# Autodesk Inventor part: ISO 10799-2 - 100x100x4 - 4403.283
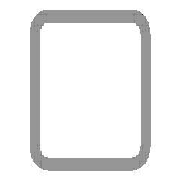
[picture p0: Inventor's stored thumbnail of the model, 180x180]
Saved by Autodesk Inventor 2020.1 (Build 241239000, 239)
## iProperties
Created: 2019-10
Part Number: ISO 10799-2 - 100x100x4 - 4403.283
Material: Stainless Steel
Description: Structural steels - Cold-formed, welded, structural hollow sections
Document SubType Name: Modeling
Standard: ISO
Designer: Synergysoft Dell02
Standard Revision: First edition 2011-09-15
Standards Organization: ISO
Language: en-US
Size Designation: 100x100x4
Categories: <MemberInstance><Categories><Category DisplayName="Structural Shapes" InternalName="089c4875-fa83-4c05-b084-43b9cc11f5ed" Mnemonic="GRDR"><CategoryParameter Dis
Stock Number: 100x100x4
Density: 8 g/cm^3
Appearance: Semi-Polished
_CCFamilyMember: 43
_CCFamilyDisplayName: ISO 10799-2 (Square) - Structural steels - Cold-formed, welded, structural hollow sections
_FrameMemberDoc: Frame Member File
_Version: 15.0.0
_GetPNFromCC: 1
G_L: 4403.283 mm
G_W: 100.000 mm
G_H: 100.000 mm
+F0EB09D6-E95E-4F0D-A0A9-255925CD8DEC+CUTDETAIL1: Miter 45.00 deg
+C07F1630-128D-4BA2-99A7-A66D939FA75D+CUTDETAIL2: Miter 22.50 deg
IsCustomPart: 1
Author: Synergysoft Dell02
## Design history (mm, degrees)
node "Start Plane"
node "End Plane"
sketch "Sketch"
  geometry: L1 (-50, -42)-(-50, 42); L2 (-42, 50)-(42, 50); L3 (50, 42)-(50, -42); L4 (42, -50)-(-42, -50); L5 (-42, 46)-(42, 46); L6 (46, 42)-(46, -42); L7 (42, -46)-(-42, -46); L8 (-46, -42)-(-46, 42); L9 (0, 72.32)-(0, -72.32) reference; L10 (-72.32, 0)-(72.32, 0) reference; A1 r 8 centre (-42, -42) between (-50, -42) and (-42, -50); A2 r 8 centre (42, 42) between (50, 42) and (42, 50); A3 r 8 centre (-42, 42) between (-42, 50) and (-50, 42); A4 r 8 centre (42, -42) between (42, -50) and (50, -42); A5 r 4 centre (-42, 42) between (-42, 46) and (-46, 42); A6 r 4 centre (42, 42) between (46, 42) and (42, 46); A7 r 4 centre (42, -42) between (42, -46) and (46, -42); A8 r 4 centre (-42, -42) between (-46, -42) and (-42, -46)
  constraints: 16 end point, 16 point on circle, 8 centre point, 8 tangent, 4 parallel, 3 equal radius, 2 perpendicular, 7 other
  dimensions: "d7" = 8 radius of A1 (= G_IR); "d9" = 100 distance between parallel lines of L1 L3 (= G_W); "d11" = 100 distance between parallel lines of L2 L4 (= G_H); "d12" = 4 distance between parallel lines of L3 L6 (= G_T); "d15" = 50 distance between parallel lines of L9 L3 (= 0.5 x d9); "d16" = 50 distance between parallel lines of L2 L10 (= 0.5 x d11)
extrude "Body" new body sketch "Sketch" stored distance "d3" = 4403.28302 (= G_L); taper "d4" = 0 deg
node "Driven Length"
  sketch "Sketch3"
    geometry: L1 (0, 0)-(10, 0) reference
    constraints: 2 end point, 1 horizontal
  workplane "Work Plane3"
  sketch "Sketch4"
    geometry: L1 (-2, -114.178)-(12, -114.178) reference; L2 (-2, 4289.105)-(12, 4289.105) reference
    dimensions: "d18" = 4403.28302 distance between parallel lines of L1 L2 (derived)
workplane "Work Plane4"
split "Split1"
workplane "Work Plane5"
split "Split2"
body "Solid1"
other parameters: "G_W" = 100 [user parameter; used in 1 equation term], "G_H" = 100 [user parameter; used in 1 equation term], "G_T" = 4 [user parameter; used in 1 equation term], "G_IR" = 8 [user parameter; used in 1 equation term], "G_L" = 4403.28302 (= d18) [user parameter; used in 1 equation term], "G_OFFSET_START" = 114.17786 [user parameter; used in 1 equation term], "G_OFFSET_END" = 46.46447 [user parameter; used in 1 equation term], "d13" = -114.17786 (= -G_OFFSET_START), "d14" = 4289.10515 (= G_OFFSET_END + B_L), "B_L" = 4242.64069 [user parameter; used in 1 equation term], "d17" = 90 deg, "MAS" = 1.17 [user parameter]
